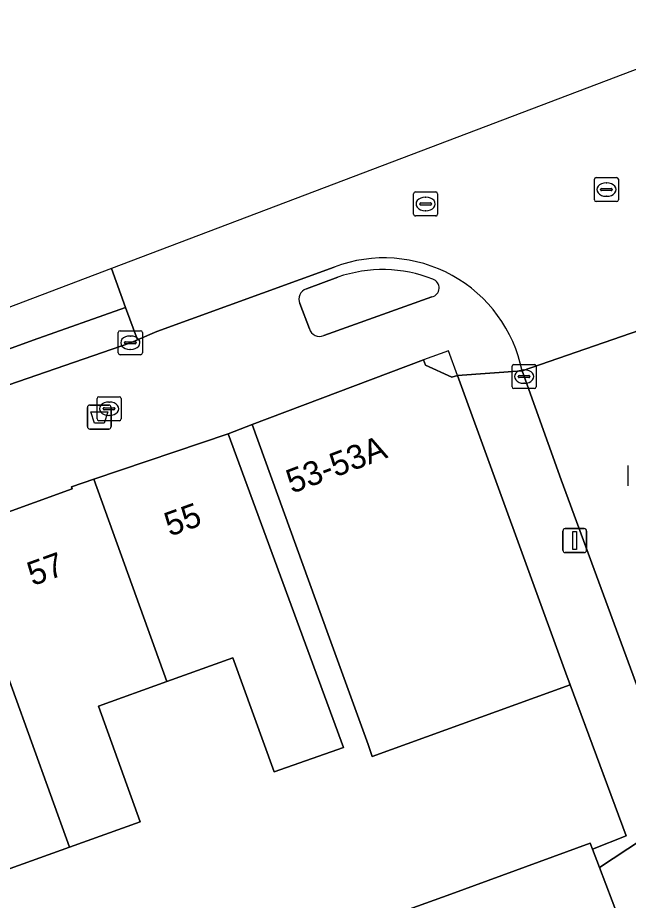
# Model space of a CAD drawing. Extents: x 159499 to 160349, y 382524 to 383273.
# Drawn here: x 159751.59 to 159777.01, y 383112.66 to 383149.41 of the extents above; entities that cross this region are included whole.
import ezdxf

# ---------------------------------------------------------------- set-up
doc = ezdxf.new("R2010")
doc.units = 0
for name, color, linetype in [('IMGEO_Afvalbak', 7, 'Continuous'), ('IMGEO_Brandkraan', 7, 'Continuous'), ('IMGEO_Erf', 7, 'Continuous'), ('IMGEO_Groenvoorziening', 7, 'Continuous'), ('IMGEO_Kolk', 7, 'Continuous'), ('IMGEO_Lichtmast', 7, 'Continuous'), ('IMGEO_Muur', 7, 'Continuous'), ('IMGEO_Pand', 7, 'Continuous'), ('IMGEO_Pand_nummerreeks', 7, 'Continuous'), ('IMGEO_Pand_overbouw', 7, 'Continuous'), ('IMGEO_Rijbaan_lokaal_gesloten', 7, 'Continuous'), ('IMGEO_Rijbaan_lokaal_open', 7, 'Continuous'), ('IMGEO_Rioolput', 7, 'Continuous'), ('IMGEO_Voetpad_open', 7, 'Continuous')]:
    doc.layers.add(name, color=color, linetype=linetype)

msp = doc.modelspace()

# ---------------------------------------------------------------- linework, layer by layer
at = {"layer": 'IMGEO_Afvalbak'}
for p, q in [((159754.59, 383133.285), (159755.38, 383133.285)), ((159755.38, 383133.285), (159754.59, 383133.285)), ((159754.49, 383132.385), (159754.49, 383133.185)), ((159754.49, 383133.185), (159754.49, 383132.385)), ((159755.48, 383133.185), (159755.48, 383132.385)), ((159755.48, 383132.385), (159755.48, 383133.185)), ((159755.38, 383132.285), (159754.59, 383132.285)), ((159754.59, 383132.285), (159755.38, 383132.285))]:
    msp.add_line(p, q, dxfattribs=at)
msp.add_lwpolyline([(159754.633, 383132.999), (159755.337, 383132.999), (159755.188, 383132.529), (159754.782, 383132.529), (159754.633, 383132.999)], dxfattribs=at)
for centre, start, end in [((159754.59, 383133.185), 90, 180), ((159754.59, 383133.185), 90, 180), ((159755.38, 383133.185), 0, 90), ((159755.38, 383133.185), 360, 90), ((159754.59, 383132.385), 180, 270), ((159754.59, 383132.385), 180, 270), ((159755.38, 383132.385), 270, 0), ((159755.38, 383132.385), 270, 0)]:
    msp.add_arc(centre, 0.1, start, end, dxfattribs=at)
at = {"layer": 'IMGEO_Brandkraan'}
for p, q in [((159754.97, 383133.629), (159755.822, 383133.629)), ((159754.895, 383132.703), (159754.895, 383133.555)), ((159755.383, 383133.409), (159755.408, 383133.409)), ((159755.896, 383133.555), (159755.896, 383132.703)), ((159755.154, 383133.123), (159755.154, 383133.135)), ((159755.592, 383133.086), (159755.194, 383133.086)), ((159755.197, 383133.172), (159755.595, 383133.172)), ((159755.406, 383132.849), (159755.381, 383132.849)), ((159755.638, 383133.135), (159755.638, 383133.123)), ((159755.822, 383132.629), (159754.97, 383132.629))]:
    msp.add_line(p, q, dxfattribs=at)
for points in [[(159754.97, 383133.629), (159755.822, 383133.629)], [(159754.895, 383132.703), (159754.895, 383133.555)], [(159755.896, 383133.555), (159755.896, 383132.703)], [(159755.822, 383132.629), (159754.97, 383132.629)]]:
    msp.add_lwpolyline(points, dxfattribs=at)
for centre, radius, start, end in [((159754.972, 383133.553), 0.0765, 91.552, 178.448), ((159754.972, 383133.553), 0.0765, 91.552, 178.448), ((159755.82, 383133.553), 0.0765, 1.552, 88.448), ((159755.82, 383133.553), 0.0765, 1.552, 88.448), ((159755.194, 383133.132), 0.0403, 85.8775, 175.7526), ((159755.191, 383133.122), 0.0366, 178.938, 274.7102), ((159755.595, 383133.129), 0.043, 264.8664, 352.4533), ((159755.599, 383133.134), 0.0386, 1.7309, 96.639), ((159754.972, 383132.705), 0.0765, 181.552, 268.448), ((159754.972, 383132.705), 0.0765, 181.552, 268.448), ((159755.82, 383132.705), 0.0765, 271.552, 358.448), ((159755.82, 383132.705), 0.0765, 271.552, 358.448)]:
    msp.add_arc(centre, radius, start, end, dxfattribs=at)
for centre, major_axis, ratio, start_param, end_param in [((159755.382, 383133.129), (-0.387, 0.002), 0.722429, 4.712389, 7.853982), ((159755.407, 383133.129), (-0.39, 0.002), 0.717154, 1.570796, 4.712389)]:
    msp.add_ellipse(centre, major_axis=major_axis, ratio=ratio, start_param=start_param, end_param=end_param, dxfattribs=at)
at = {"layer": 'IMGEO_Erf'}
msp.add_lwpolyline([(159767.542, 383112.172), (159769.614, 383112.927), (159775.419, 383115.043), (159775.511, 383114.801), (159776.913, 383115.349), (159774.59, 383121.63), (159766.35, 383118.659), (159766.172, 383119.152), (159764.518, 383123.737), (159761.345, 383132.467), (159760.352, 383132.09), (159765.147, 383119.021), (159762.26, 383118.01), (159760.546, 383122.764), (159757.795, 383121.772), (159754.952, 383120.746), (159756.686, 383115.938), (159753.74, 383114.875), (159750.935, 383113.863)], dxfattribs=at)
at = {"layer": 'IMGEO_Groenvoorziening'}
for points in [[(159764.915, 383138.605), (159763.604, 383138.115)], [(159764.329, 383136.178), (159768.827, 383137.789)], [(159763.327, 383137.511), (159763.73, 383136.451)]]:
    msp.add_lwpolyline(points, dxfattribs=at)
for centre, radius, start, end in [((159766.778, 383133.313), 5.61, 68.1659, 109.3976), ((159768.756, 383138.16), 0.377, 280.8251, 73.2315), ((159763.743, 383137.686), 0.451, 107.8968, 202.83), ((159764.155, 383136.589), 0.446, 198.0085, 292.9884)]:
    msp.add_arc(centre, radius, start, end, dxfattribs=at)
at = {"layer": 'IMGEO_Kolk'}
for p, q in [((159755.778, 383135.452), (159755.778, 383136.304)), ((159755.853, 383136.378), (159756.705, 383136.378)), ((159756.266, 383136.158), (159756.291, 383136.158)), ((159756.779, 383136.304), (159756.779, 383135.452)), ((159756.037, 383135.872), (159756.037, 383135.884)), ((159756.475, 383135.835), (159756.077, 383135.835)), ((159756.08, 383135.921), (159756.478, 383135.921)), ((159756.521, 383135.884), (159756.521, 383135.872)), ((159756.289, 383135.598), (159756.264, 383135.598)), ((159756.705, 383135.378), (159755.853, 383135.378)), ((159772.166, 383134.044), (159772.166, 383134.896)), ((159772.241, 383134.97), (159773.093, 383134.97)), ((159772.654, 383134.75), (159772.679, 383134.75)), ((159773.167, 383134.896), (159773.167, 383134.044)), ((159772.425, 383134.464), (159772.425, 383134.476)), ((159772.863, 383134.427), (159772.465, 383134.427)), ((159772.468, 383134.513), (159772.866, 383134.513)), ((159772.909, 383134.476), (159772.909, 383134.464)), ((159773.093, 383133.97), (159772.241, 383133.97)), ((159772.677, 383134.19), (159772.652, 383134.19))]:
    msp.add_line(p, q, dxfattribs=at)
for points in [[(159755.778, 383135.452), (159755.778, 383136.304)], [(159755.853, 383136.378), (159756.705, 383136.378)], [(159756.779, 383136.304), (159756.779, 383135.452)], [(159756.705, 383135.378), (159755.853, 383135.378)], [(159772.166, 383134.044), (159772.166, 383134.896)], [(159772.241, 383134.97), (159773.093, 383134.97)], [(159773.167, 383134.896), (159773.167, 383134.044)], [(159773.093, 383133.97), (159772.241, 383133.97)]]:
    msp.add_lwpolyline(points, dxfattribs=at)
for centre, radius, start, end in [((159755.855, 383136.302), 0.0765, 91.552, 178.448), ((159755.855, 383136.302), 0.0765, 91.552, 178.448), ((159756.703, 383136.302), 0.0765, 1.552, 88.448), ((159756.703, 383136.302), 0.0765, 1.552, 88.448), ((159756.077, 383135.881), 0.0403, 85.8775, 175.7526), ((159756.074, 383135.871), 0.0366, 178.938, 274.7102), ((159756.478, 383135.878), 0.043, 264.8664, 352.4533), ((159756.482, 383135.883), 0.0386, 1.7309, 96.639), ((159755.855, 383135.454), 0.0765, 181.552, 268.448), ((159755.855, 383135.454), 0.0765, 181.552, 268.448), ((159756.703, 383135.454), 0.0765, 271.552, 358.448), ((159756.703, 383135.454), 0.0765, 271.552, 358.448), ((159772.243, 383134.894), 0.0765, 91.552, 178.448), ((159772.243, 383134.894), 0.0765, 91.552, 178.448), ((159773.091, 383134.894), 0.0765, 1.552, 88.448), ((159773.091, 383134.894), 0.0765, 1.552, 88.448), ((159772.465, 383134.473), 0.0403, 85.8775, 175.7526), ((159772.462, 383134.463), 0.0366, 178.938, 274.7102), ((159772.866, 383134.47), 0.043, 264.8664, 352.4533), ((159772.87, 383134.475), 0.0386, 1.7309, 96.639), ((159772.243, 383134.046), 0.0765, 181.552, 268.448), ((159772.243, 383134.046), 0.0765, 181.552, 268.448), ((159773.091, 383134.046), 0.0765, 271.552, 358.448), ((159773.091, 383134.046), 0.0765, 271.552, 358.448)]:
    msp.add_arc(centre, radius, start, end, dxfattribs=at)
for centre, major_axis, ratio, start_param, end_param in [((159756.265, 383135.878), (-0.387, 0.002), 0.722429, 4.712389, 7.853982), ((159756.29, 383135.878), (-0.39, 0.002), 0.717154, 1.570796, 4.712389), ((159772.653, 383134.47), (-0.387, 0.002), 0.722429, 4.712389, 7.853982), ((159772.678, 383134.47), (-0.39, 0.002), 0.717154, 1.570796, 4.712389)]:
    msp.add_ellipse(centre, major_axis=major_axis, ratio=ratio, start_param=start_param, end_param=end_param, dxfattribs=at)
at = {"layer": 'IMGEO_Lichtmast'}
for p, q in [((159774.38, 383128.14), (159775.17, 383128.14)), ((159775.17, 383128.14), (159774.38, 383128.14)), ((159774.28, 383127.24), (159774.28, 383128.04)), ((159774.28, 383128.04), (159774.28, 383127.24)), ((159775.27, 383128.04), (159775.27, 383127.24)), ((159775.27, 383127.24), (159775.27, 383128.04)), ((159775.17, 383127.14), (159774.38, 383127.14)), ((159774.38, 383127.14), (159775.17, 383127.14))]:
    msp.add_line(p, q, dxfattribs=at)
msp.add_lwpolyline([(159774.7, 383128.015), (159774.85, 383128.015), (159774.85, 383127.265), (159774.7, 383127.265), (159774.7, 383128.015)], dxfattribs=at)
for centre, start, end in [((159774.38, 383128.04), 90, 180), ((159774.38, 383128.04), 90, 180), ((159775.17, 383128.04), 0, 90), ((159775.17, 383128.04), 360, 90), ((159774.38, 383127.24), 180, 270), ((159774.38, 383127.24), 180, 270), ((159775.17, 383127.24), 270, 0), ((159775.17, 383127.24), 270, 0)]:
    msp.add_arc(centre, 0.1, start, end, dxfattribs=at)
at = {"layer": 'IMGEO_Muur'}
msp.add_lwpolyline([(159776.913, 383115.349), (159774.41, 383122.123)], dxfattribs=at)
at = {"layer": 'IMGEO_Pand'}
for points in [[(159769.889, 383134.514), (159769.653, 383134.441), (159768.561, 383134.939), (159768.476, 383135.163), (159761.345, 383132.467), (159764.518, 383123.737), (159766.172, 383119.152), (159766.35, 383118.659), (159774.59, 383121.63), (159774.41, 383122.123)], [(159754.755, 383130.199), (159757.795, 383121.772), (159760.546, 383122.764), (159762.26, 383118.01), (159765.147, 383119.021), (159760.352, 383132.09)], [(159754.755, 383130.199), (159753.826, 383129.885), (159753.858, 383129.791), (159748.99, 383128.04), (159753.74, 383114.875), (159756.686, 383115.938), (159754.952, 383120.746), (159757.795, 383121.772)], [(159753.74, 383114.875), (159748.99, 383128.04), (159744.007, 383126.247), (159743.973, 383126.341), (159743.847, 383126.296), (159745.57, 383121.517), (159746.877, 383117.921), (159749.167, 383118.766), (159750.935, 383113.863)], [(159775.805, 383114.025), (159775.511, 383114.801), (159775.419, 383115.043), (159769.614, 383112.927), (159767.542, 383112.172), (159767.968, 383110.969), (159768.861, 383108.493), (159776.75, 383111.531), (159776.59, 383111.952)]]:
    msp.add_lwpolyline(points, close=True, dxfattribs=at)
at = {"layer": 'IMGEO_Pand_overbouw'}
msp.add_lwpolyline([(159768.476, 383135.163), (159768.561, 383134.939), (159769.653, 383134.441), (159769.889, 383134.514), (159769.519, 383135.545)], close=True, dxfattribs=at)
at = {"layer": 'IMGEO_Rijbaan_lokaal_gesloten'}
msp.add_lwpolyline([(159739.519, 383129.834), (159740.196, 383130.062), (159741.348, 383130.496), (159746.868, 383132.494), (159748.478, 383133.177), (159756.279, 383135.878), (159756.578, 383136.003), (159756.081, 383137.35), (159752.24, 383135.984), (159747.882, 383134.405), (159722.071, 383125.09), (159713.516, 383121.988)], dxfattribs=at)
at = {"layer": 'IMGEO_Rijbaan_lokaal_open'}
for points in [[(159781.267, 383145.689), (159780.528, 383147.266), (159783.129, 383148.501), (159782.678, 383149.411), (159782.186, 383149.098), (159767.963, 383143.697), (159755.499, 383138.964)], [(159755.499, 383138.964), (159713.146, 383122.881)], [(159713.516, 383121.988), (159722.071, 383125.09), (159747.882, 383134.405), (159752.24, 383135.984), (159756.081, 383137.35), (159755.499, 383138.964)], [(159755.499, 383138.964), (159756.081, 383137.35), (159756.578, 383136.003), (159757.38, 383136.339), (159764.768, 383139.029)], [(159772.581, 383134.709), (159778.611, 383136.792), (159778.248, 383137.836)], [(159787.42, 383112.738), (159786.637, 383114.776), (159781.272, 383129.409), (159779.368, 383134.611), (159778.611, 383136.792), (159772.581, 383134.709), (159774.207, 383130.173), (159779.295, 383116.33), (159780.557, 383112.866), (159781.723, 383109.665), (159782.266, 383108.252), (159784.675, 383101.976), (159785.579, 383099.622), (159787.251, 383095.622), (159788.654, 383092.265), (159790.487, 383087.878), (159792.286, 383084.017), (159792.884, 383082.767), (159793.423, 383082.246), (159794.818, 383081.903)]]:
    msp.add_lwpolyline(points, dxfattribs=at)
msp.add_arc((159766.843, 383133.556), 5.853, 11.3628, 110.7587, dxfattribs=at)
at = {"layer": 'IMGEO_Rioolput'}
for p, q in [((159775.592, 383141.829), (159775.592, 383142.681)), ((159775.667, 383142.755), (159776.519, 383142.755)), ((159776.08, 383142.535), (159776.105, 383142.535)), ((159776.593, 383142.681), (159776.593, 383141.829)), ((159768.068, 383141.228), (159768.068, 383142.08)), ((159768.143, 383142.154), (159768.995, 383142.154)), ((159769.069, 383142.08), (159769.069, 383141.228)), ((159775.851, 383142.249), (159775.851, 383142.261)), ((159776.289, 383142.212), (159775.891, 383142.212)), ((159775.894, 383142.298), (159776.292, 383142.298)), ((159776.335, 383142.261), (159776.335, 383142.249)), ((159768.327, 383141.648), (159768.327, 383141.66)), ((159768.37, 383141.697), (159768.768, 383141.697)), ((159768.556, 383141.934), (159768.581, 383141.934)), ((159768.811, 383141.66), (159768.811, 383141.648)), ((159776.519, 383141.755), (159775.667, 383141.755)), ((159776.103, 383141.975), (159776.078, 383141.975)), ((159768.765, 383141.611), (159768.367, 383141.611)), ((159768.579, 383141.374), (159768.554, 383141.374)), ((159768.995, 383141.154), (159768.143, 383141.154)), ((159777.005, 383129.917), (159777.005, 383130.769))]:
    msp.add_line(p, q, dxfattribs=at)
for points in [[(159775.592, 383141.829), (159775.592, 383142.681)], [(159775.667, 383142.755), (159776.519, 383142.755)], [(159776.593, 383142.681), (159776.593, 383141.829)], [(159768.068, 383141.228), (159768.068, 383142.08)], [(159768.143, 383142.154), (159768.995, 383142.154)], [(159769.069, 383142.08), (159769.069, 383141.228)], [(159776.519, 383141.755), (159775.667, 383141.755)], [(159768.995, 383141.154), (159768.143, 383141.154)], [(159777.005, 383129.917), (159777.005, 383130.769)]]:
    msp.add_lwpolyline(points, dxfattribs=at)
for centre, radius, start, end in [((159775.669, 383142.679), 0.0765, 91.552, 178.448), ((159775.669, 383142.679), 0.0765, 91.552, 178.448), ((159776.517, 383142.679), 0.0765, 1.552, 88.448), ((159776.517, 383142.679), 0.0765, 1.552, 88.448), ((159768.145, 383142.078), 0.0765, 91.552, 178.448), ((159768.145, 383142.078), 0.0765, 91.552, 178.448), ((159768.993, 383142.078), 0.0765, 1.552, 88.448), ((159768.993, 383142.078), 0.0765, 1.552, 88.448), ((159775.891, 383142.258), 0.0403, 85.8775, 175.7526), ((159775.888, 383142.248), 0.0366, 178.938, 274.7102), ((159776.292, 383142.255), 0.043, 264.8664, 352.4533), ((159776.296, 383142.26), 0.0386, 1.7309, 96.639), ((159768.367, 383141.657), 0.0403, 85.8775, 175.7526), ((159768.772, 383141.659), 0.0386, 1.7309, 96.639), ((159775.669, 383141.831), 0.0765, 181.552, 268.448), ((159775.669, 383141.831), 0.0765, 181.552, 268.448), ((159776.517, 383141.831), 0.0765, 271.552, 358.448), ((159776.517, 383141.831), 0.0765, 271.552, 358.448), ((159768.364, 383141.647), 0.0366, 178.938, 274.7102), ((159768.768, 383141.654), 0.043, 264.8664, 352.4533), ((159768.145, 383141.23), 0.0765, 181.552, 268.448), ((159768.145, 383141.23), 0.0765, 181.552, 268.448), ((159768.993, 383141.23), 0.0765, 271.552, 358.448), ((159768.993, 383141.23), 0.0765, 271.552, 358.448)]:
    msp.add_arc(centre, radius, start, end, dxfattribs=at)
for centre, major_axis, ratio, start_param, end_param in [((159776.079, 383142.255), (-0.387, 0.002), 0.722429, 4.712389, 7.853982), ((159776.104, 383142.255), (-0.39, 0.002), 0.717154, 1.570796, 4.712389), ((159768.555, 383141.654), (-0.387, 0.002), 0.722429, 4.712389, 7.853982), ((159768.58, 383141.654), (-0.39, 0.002), 0.717154, 1.570796, 4.712389)]:
    msp.add_ellipse(centre, major_axis=major_axis, ratio=ratio, start_param=start_param, end_param=end_param, dxfattribs=at)
at = {"layer": 'IMGEO_Voetpad_open'}
for points in [[(159764.768, 383139.029), (159757.38, 383136.339), (159756.578, 383136.003), (159756.279, 383135.878), (159748.478, 383133.177), (159746.868, 383132.494), (159741.348, 383130.496), (159740.196, 383130.062)], [(159763.604, 383138.115), (159764.915, 383138.605)], [(159768.827, 383137.789), (159764.329, 383136.178)], [(159763.73, 383136.451), (159763.327, 383137.511)], [(159748.99, 383128.04), (159753.858, 383129.791), (159753.826, 383129.885), (159754.755, 383130.199), (159760.352, 383132.09), (159761.345, 383132.467), (159768.476, 383135.163), (159768.561, 383134.939), (159769.653, 383134.441), (159769.889, 383134.514), (159772.581, 383134.709)]]:
    msp.add_lwpolyline(points, dxfattribs=at)
for points in [[(159774.207, 383130.173), (159772.581, 383134.709), (159769.889, 383134.514), (159774.41, 383122.123), (159774.59, 383121.63), (159776.913, 383115.349), (159775.511, 383114.801), (159775.805, 383114.025), (159779.295, 383116.33)], [(159776.59, 383111.952), (159780.557, 383112.866), (159779.295, 383116.33), (159775.805, 383114.025)]]:
    msp.add_lwpolyline(points, close=True, dxfattribs=at)
for centre, radius, start, end in [((159766.843, 383133.556), 5.853, 11.3628, 110.7587), ((159766.778, 383133.313), 5.61, 68.1659, 109.3976), ((159768.756, 383138.16), 0.377, 280.8251, 73.2315), ((159763.743, 383137.686), 0.451, 107.8968, 202.83), ((159764.155, 383136.589), 0.446, 198.0085, 292.9884)]:
    msp.add_arc(centre, radius, start, end, dxfattribs=at)

# ---------------------------------------------------------------- texts
at = {"layer": 'IMGEO_Pand_nummerreeks'}
for s, rotation, p in [('53-53A', 20.7067, (159763.004, 383129.587)), ('55', 19.8342, (159757.921, 383127.801)), ('57', 19.8392, (159752.212, 383125.741))]:
    msp.add_text(s, height=1, rotation=rotation, dxfattribs=at).set_placement(p)

doc.saveas('drawing.dxf')
